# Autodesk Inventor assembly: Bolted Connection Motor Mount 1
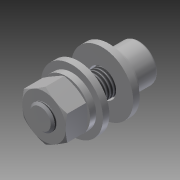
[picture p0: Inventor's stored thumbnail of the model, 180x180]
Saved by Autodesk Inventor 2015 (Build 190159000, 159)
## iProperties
Created: 2007-02
Part Number: Bolted Connection Motor Mount 1
Document SubType Name: Assembly
Designer: Autodesk, Inc.
Mass: 17.5979 g
Surface Area: 26.518 cm^2
Volume: 2.23891 cm^3
Density: 7.86 g/cm^3
ClientObjectVersion: 1
Author: Autodesk, Inc.
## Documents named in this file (5)
- C:\Users\Public\Documents\Autodesk\Inventor 2015\Samples\Models\Assemblies\Blower\Blower\Design Accelerator\Bolted Connection Drive Casing1.iam
- C:\Users\Public\Documents\Autodesk\Inventor 2015\Samples\Standard Parts\en-US\ANSI B18.22.1\ANSI B18.22.1 - 1_4 - narrow - Type A.ipt
- C:\Users\Public\Documents\Autodesk\Inventor 2015\Samples\Standard Parts\en-US\ANSI B18.21.1\ANSI B18.21.1 - 0.25.ipt
- C:\Users\Public\Documents\Autodesk\Inventor 2015\Samples\Standard Parts\en-US\ANSI B18.3(13)\ANSI B18.3 - 1_4-28 UNF - 0.75(22).ipt
- C:\Users\Public\Documents\Autodesk\Inventor 2015\Samples\Standard Parts\en-US\ANSI B18.2.2(09)\ANSI B18.2.2 - 1_4 - 28(2).ipt
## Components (6 placed, 4 different names)
1. ANSI B18.22.1 - 1/4 - narrow - Type A:1
2. ANSI B18.21.1 - 0.25:2
3. ANSI B18.3 - 1/4-28 UNF - 0.75:3
4. ANSI B18.22.1 - 1/4 - narrow - Type A:4
5. ANSI B18.21.1 - 0.25:5
6. ANSI B18.2.2 - 1/4 - 28:6
